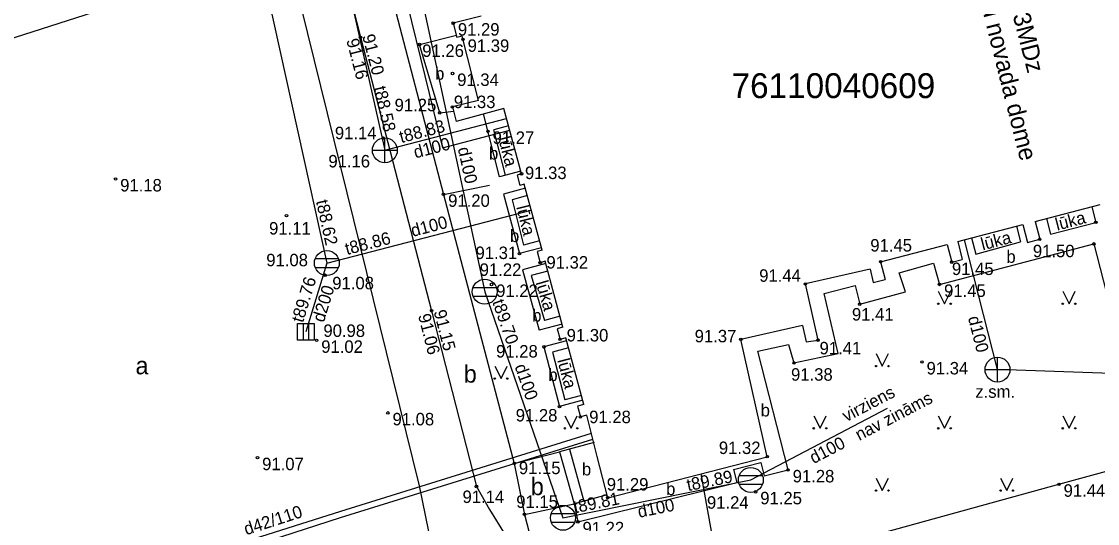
# Model space of a CAD drawing. Extents: x 634272 to 634544, y 247463 to 247653.
# Drawn here: x 634375.43 to 634418.64, y 247553.68 to 247573.83 of the extents above; entities that cross this region are included whole.
import ezdxf

# ---------------------------------------------------------------- set-up
doc = ezdxf.new("R2010")
doc.units = 0
for name, color, linetype in [('BUVE_BDET_####_####_#', 7, 'Continuous'), ('BUVE_BDET_####_TKST_#', 7, 'Continuous'), ('BUVE_EKAS_####_####_#', 7, 'Continuous'), ('BUVE_EKAS_BIZM_TKST_#', 7, 'Continuous'), ('BUVE_EKAS_RAKS_TKST_#', 7, 'Continuous'), ('CELI_CAPM_####_####_#', 7, 'Continuous'), ('CELI_CMAL_####_####_#', 7, 'Continuous'), ('CELI_CSEG_####_TKST_#', 7, 'Continuous'), ('ELEK_VADP_ZSPR_####_#', 7, 'Continuous'), ('LKAN_ELEM_####_####_#', 7, 'Continuous'), ('LKAN_ELEM_PAST_TKST_#', 7, 'Continuous'), ('LKAN_VADP_PAST_####_#', 7, 'Continuous'), ('LKAN_VADP_PAST_TKST_#', 7, 'Continuous'), ('RELJ_AATZ_####_TKST_#', 7, 'Continuous'), ('RELJ_ELEM_####_####_#', 7, 'Continuous'), ('ROBZ_KADS_####_TKST_#', 7, 'Continuous'), ('SILT_VADP_UDEN_####_#', 7, 'Continuous'), ('SILT_VADP_UDEN_TKST_#', 7, 'Continuous'), ('SKAN_ELEM_####_####_#', 7, 'Continuous'), ('SKAN_ELEM_PAST_TKST_#', 7, 'Continuous'), ('SKAN_VADP_PAST_####_#', 7, 'Continuous'), ('SKAN_VADP_PAST_TKST_#', 7, 'Continuous'), ('TERT_ELEM_####_####_#', 7, 'Continuous'), ('UDTK_VADP_NEDR_####_#', 7, 'Continuous'), ('UDTK_VADP_UDEN_####_#', 7, 'Continuous')]:
    doc.layers.add(name, color=color, linetype=linetype)

msp = doc.modelspace()

# ---------------------------------------------------------------- linework, layer by layer
at = {"layer": 'BUVE_BDET_####_####_#'}
for p, q in [((634394.989, 247569.64), (634394.404, 247569.482)), ((634394.865, 247567.656), (634394.404, 247569.482)), ((634395.48, 247567.827), (634394.623, 247567.595)), ((634395.665, 247567.141), (634394.783, 247566.902)), ((634395.746, 247566.844), (634395.133, 247566.678)), ((634418.412, 247566.397), (634418.576, 247565.768)), ((634415.389, 247565.61), (634415.553, 247564.98)), ((634416.592, 247565.923), (634416.756, 247565.292)), ((634396.312, 247564.751), (634395.427, 247564.512)), ((634396.236, 247565.032), (634395.59, 247564.857)), ((634413.588, 247565.141), (634413.758, 247564.489)), ((634396.485, 247564.111), (634395.553, 247563.859)), ((634396.566, 247563.811), (634395.902, 247563.631)), ((634397.141, 247561.686), (634396.223, 247561.438)), ((634397.056, 247561.999), (634396.43, 247561.83)), ((634397.322, 247561.016), (634396.412, 247560.77)), ((634397.398, 247560.737), (634396.749, 247560.561)), ((634397.916, 247558.82), (634397.253, 247558.641)), ((634397.969, 247558.625), (634397.035, 247558.372)), ((634398.427, 247556.933), (634397.042, 247556.558)), ((634397.432, 247556.663), (634398.017, 247554.574)), ((634404.03, 247555.842), (634405.124, 247556.123)), ((634405.124, 247556.123), (634405.26, 247555.594)), ((634404.03, 247555.842), (634404.163, 247555.323)), ((634398.948, 247554.826), (634397.627, 247554.469)), ((634397.627, 247554.469), (634397.775, 247553.745))]:
    msp.add_line(p, q, dxfattribs=at)
for points in [[(634392.223, 247570.162), (634391.414, 247572.908), (634392.893, 247573.281)], [(634392.223, 247570.162), (634392.776, 247570.234)], [(634394.623, 247567.595), (634393.985, 247570.121)], [(634394.783, 247566.902), (634395.427, 247564.512)], [(634395.133, 247566.678), (634395.59, 247564.857)], [(634416.756, 247565.292), (634418.576, 247565.768)], [(634406.216, 247555.83), (634405.003, 247560.603), (634406.24, 247560.87), (634406.454, 247560.126), (634408.225, 247560.507), (634407.669, 247562.916), (634408.905, 247563.238), (634409.092, 247562.484), (634410.939, 247562.975), (634410.684, 247563.745), (634412.053, 247564.132), (634412.297, 247563.275), (634418.496, 247564.903), (634419.89, 247559.492), (634422.401, 247560.131), (634422.592, 247559.464)], [(634413.758, 247564.489), (634415.553, 247564.98)], [(634395.553, 247563.859), (634396.223, 247561.438)], [(634395.902, 247563.631), (634396.43, 247561.83)], [(634396.412, 247560.77), (634397.035, 247558.372)], [(634396.749, 247560.561), (634397.253, 247558.641)], [(634397.042, 247556.558), (634397.627, 247554.469)], [(634405.26, 247555.594), (634406.216, 247555.83)], [(634397.775, 247553.745), (634404.163, 247555.323)]]:
    msp.add_lwpolyline(points, dxfattribs=at)
at = {"layer": 'BUVE_EKAS_####_####_#'}
for p, q in [((634393.887, 247574.04), (634392.768, 247573.764)), ((634393.126, 247573.244), (634392.916, 247573.19)), ((634393.779, 247570.663), (634393.126, 247573.244)), ((634393.779, 247570.663), (634392.734, 247570.399)), ((634394.799, 247570.341), (634392.88, 247569.822)), ((634395.51, 247567.715), (634395.333, 247567.667)), ((634395.623, 247567.295), (634395.443, 247567.247)), ((634415.648, 247565.677), (634415.834, 247564.962)), ((634416.138, 247565.805), (634416.324, 247565.09)), ((634412.601, 247564.884), (634412.788, 247564.169)), ((634413.028, 247564.995), (634413.214, 247564.28)), ((634396.337, 247564.656), (634396.135, 247564.602)), ((634396.135, 247564.602), (634396.254, 247564.149)), ((634396.46, 247564.205), (634396.254, 247564.149)), ((634409.511, 247563.883), (634406.911, 247563.295)), ((634409.511, 247563.883), (634409.632, 247563.347)), ((634409.932, 247564.189), (634410.112, 247563.472)), ((634397.175, 247561.56), (634396.947, 247561.498)), ((634396.947, 247561.498), (634397.059, 247561.07)), ((634406.798, 247561.628), (634404.32, 247561.069)), ((634406.798, 247561.628), (634406.947, 247560.969)), ((634397.291, 247561.133), (634397.059, 247561.07)), ((634398.015, 247558.453), (634397.761, 247558.384)), ((634397.761, 247558.384), (634397.873, 247557.957)), ((634398.131, 247558.027), (634397.873, 247557.957))]:
    msp.add_line(p, q, dxfattribs=at)
for points in [[(634392.768, 247573.764), (634392.916, 247573.19)], [(634392.734, 247570.399), (634392.88, 247569.822)], [(634395.51, 247567.715), (634394.799, 247570.341)], [(634395.333, 247567.667), (634395.443, 247567.247)], [(634396.337, 247564.656), (634395.623, 247567.295)], [(634416.138, 247565.805), (634418.747, 247566.484)], [(634413.028, 247564.995), (634415.648, 247565.677)], [(634409.932, 247564.189), (634412.601, 247564.884)], [(634415.834, 247564.962), (634416.324, 247565.09)], [(634412.788, 247564.169), (634413.214, 247564.28)], [(634397.175, 247561.56), (634396.46, 247564.205)], [(634409.632, 247563.347), (634410.112, 247563.472)], [(634406.947, 247560.969), (634407.421, 247561.04), (634406.911, 247563.295)], [(634398.015, 247558.453), (634397.291, 247561.133)], [(634398.975, 247554.715), (634405.382, 247556.36), (634404.32, 247561.069)], [(634398.975, 247554.715), (634398.553, 247556.371), (634398.131, 247558.027)]]:
    msp.add_lwpolyline(points, dxfattribs=at)
at = {"layer": 'CELI_CAPM_####_####_#'}
for points in [[(634386.18, 247584.245), (634386.517, 247583.098), (634389.042, 247573.196), (634391.897, 247562.219), (634393.7, 247555.164), (634394.221, 247554.237), (634394.857, 247553.225), (634395.836, 247552.623), (634399.496, 247551.073), (634400.928, 247550.806), (634417.097, 247555.253), (634426.457, 247557.809), (634427.052, 247555.379), (634437.491, 247558.047), (634462.278, 247564.311)], [(634392.378, 247566.891), (634394.229, 247567.264)]]:
    msp.add_lwpolyline(points, dxfattribs=at)
at = {"layer": 'CELI_CMAL_####_####_#'}
for points in [[(634397.071, 247591.031), (634391.102, 247589.18), (634389.241, 247588.463), (634387.877, 247587.668), (634387.466, 247585.812), (634389.236, 247579.186), (634390.091, 247575.648), (634392.378, 247566.891), (634395.219, 247556.093), (634395.631, 247554.043), (634396.02, 247552.545)], [(634395.219, 247556.093), (634397.042, 247556.558)], [(634395.631, 247554.043), (634397.627, 247554.469)]]:
    msp.add_lwpolyline(points, dxfattribs=at)
at = {"layer": 'ELEK_VADP_ZSPR_####_#'}
msp.add_lwpolyline([(634391.846, 247587.255), (634391.785, 247587.453), (634390.617, 247588.23), (634384.398, 247586.285), (634384.012, 247585.121), (634391.398, 247555.188), (634394.49, 247540.075)], dxfattribs=at)
at = {"layer": 'LKAN_ELEM_####_####_#'}
for p, q in [((634387.223, 247564.31), (634388.159, 247564.31)), ((634387.223, 247563.96), (634388.159, 247563.96)), ((634393.566, 247563.156), (634394.502, 247563.156)), ((634393.566, 247562.806), (634394.502, 247562.806)), ((634386.736, 247561.707), (634386.736, 247561.032)), ((634386.961, 247561.707), (634386.961, 247561.032)), ((634404.252, 247555.603), (634405.188, 247555.603)), ((634404.252, 247555.253), (634405.188, 247555.253)), ((634396.707, 247554.082), (634397.643, 247554.082)), ((634396.707, 247553.732), (634397.643, 247553.732))]:
    msp.add_line(p, q, dxfattribs=at)
msp.add_lwpolyline([(634386.511, 247561.707), (634387.186, 247561.707), (634387.186, 247561.032), (634386.511, 247561.032)], close=True, dxfattribs=at)
for centre in [(634387.691, 247564.135), (634394.034, 247562.981), (634404.72, 247555.428), (634397.175, 247553.907)]:
    msp.add_circle(centre, 0.5, dxfattribs=at)
at = {"layer": 'LKAN_VADP_PAST_####_#'}
for p, q in [((634381.824, 247590.733), (634387.691, 247564.135)), ((634389.021, 247586.29), (634394.034, 247562.981)), ((634387.691, 247564.135), (634386.849, 247561.369)), ((634394.034, 247562.981), (634397.175, 247553.907)), ((634397.175, 247553.907), (634404.72, 247555.428))]:
    msp.add_line(p, q, dxfattribs=at)
for points in [[(634387.691, 247564.135), (634395.903, 247566.26)], [(634404.72, 247555.428), (634410.216, 247558.304)]]:
    msp.add_lwpolyline(points, dxfattribs=at)
at = {"layer": 'RELJ_ELEM_####_####_#'}
for centre in [(634392.768, 247573.764), (634389.042, 247573.196), (634391.414, 247572.908), (634393.16, 247573.111), (634392.741, 247571.742), (634392.734, 247570.399), (634392.223, 247570.162), (634394.163, 247569.417), (634389.965, 247569.144), (634395.51, 247567.715), (634379.205, 247567.507), (634392.378, 247566.891), (634386.071, 247566.034), (634418.576, 247565.768), (634416.324, 247565.09), (634418.496, 247564.903), (634395.427, 247564.512), (634396.261, 247564.151), (634409.932, 247564.189), (634412.788, 247564.169), (634387.626, 247563.645), (634394.307, 247563.272), (634406.911, 247563.295), (634412.297, 247563.275), (634391.897, 247562.219), (634409.092, 247562.484), (634387.28, 247561.03), (634397.059, 247561.07), (634404.32, 247561.069), (634407.421, 247561.04), (634396.412, 247560.77), (634406.454, 247560.126), (634411.593, 247560.163), (634397.035, 247558.372), (634390.144, 247558.119), (634397.873, 247557.957), (634384.907, 247556.32), (634395.219, 247556.093), (634405.382, 247556.36), (634406.216, 247555.83), (634393.7, 247555.164), (634417.097, 247555.253), (634404.914, 247554.949), (634398.975, 247554.715), (634395.631, 247554.043), (634397.775, 247553.745)]:
    msp.add_circle(centre, 0.05, dxfattribs=at)
at = {"layer": 'SILT_VADP_UDEN_####_#'}
msp.add_line((634402.715, 247555.675), (634405.012, 247543.016), dxfattribs=at)
for points in [[(634375.66, 247548.71), (634375.865, 247548.771), (634375.478, 247550.132), (634388.249, 247554.171), (634398.315, 247557.303)], [(634376.217, 247548.559), (634376.441, 247548.623), (634376.038, 247549.97), (634388.236, 247553.927), (634398.375, 247557.07)]]:
    msp.add_lwpolyline(points, dxfattribs=at)
at = {"layer": 'SKAN_ELEM_####_####_#'}
for p, q in [((634390.021, 247568.162), (634390.021, 247569.162)), ((634389.521, 247568.662), (634390.521, 247568.662)), ((634414.627, 247559.359), (634414.627, 247560.359)), ((634414.127, 247559.859), (634415.127, 247559.859))]:
    msp.add_line(p, q, dxfattribs=at)
for centre in [(634390.021, 247568.662), (634414.627, 247559.859)]:
    msp.add_circle(centre, 0.5, dxfattribs=at)
at = {"layer": 'SKAN_VADP_PAST_####_#'}
for p, q in [((634386.413, 247584.687), (634390.021, 247568.662)), ((634390.021, 247568.662), (634394.908, 247569.941))]:
    msp.add_line(p, q, dxfattribs=at)
msp.add_lwpolyline([(634435.579, 247559.128), (634414.627, 247559.859), (634413.306, 247565.067)], dxfattribs=at)
at = {"layer": 'TERT_ELEM_####_####_#'}
for p, q in [((634412.25, 247563), (634412.5, 247562.5)), ((634412.5, 247562.5), (634412.75, 247563)), ((634417.25, 247563), (634417.5, 247562.5)), ((634417.5, 247562.5), (634417.75, 247563)), ((634409.75, 247560.5), (634410, 247560)), ((634410, 247560), (634410.25, 247560.5)), ((634394.437, 247559.997), (634394.687, 247559.497)), ((634394.687, 247559.497), (634394.937, 247559.997)), ((634397.25, 247558), (634397.5, 247557.5)), ((634397.5, 247557.5), (634397.75, 247558)), ((634407.25, 247558), (634407.5, 247557.5)), ((634407.5, 247557.5), (634407.75, 247558)), ((634412.25, 247558), (634412.5, 247557.5)), ((634412.5, 247557.5), (634412.75, 247558)), ((634417.25, 247558), (634417.5, 247557.5)), ((634417.5, 247557.5), (634417.75, 247558)), ((634409.75, 247555.5), (634410, 247555)), ((634410, 247555), (634410.25, 247555.5)), ((634414.75, 247555.5), (634415, 247555)), ((634415, 247555), (634415.25, 247555.5))]:
    msp.add_line(p, q, dxfattribs=at)
for centre, radius in [((634412.25, 247562.5), 0.028), ((634412.75, 247562.5), 0.0263), ((634417.25, 247562.5), 0.028), ((634417.75, 247562.5), 0.0263), ((634409.75, 247560), 0.028), ((634410.25, 247560), 0.0263), ((634394.437, 247559.496), 0.028), ((634394.937, 247559.496), 0.0263), ((634397.25, 247557.5), 0.028), ((634397.75, 247557.5), 0.0263), ((634407.25, 247557.5), 0.028), ((634407.75, 247557.5), 0.0263), ((634412.25, 247557.5), 0.028), ((634412.75, 247557.5), 0.0263), ((634417.25, 247557.5), 0.028), ((634417.75, 247557.5), 0.0263), ((634409.75, 247555), 0.028), ((634410.25, 247555), 0.0263), ((634414.75, 247555), 0.028), ((634415.25, 247555), 0.0263)]:
    msp.add_circle(centre, radius, dxfattribs=at)
at = {"layer": 'UDTK_VADP_NEDR_####_#'}
msp.add_lwpolyline([(634381.084, 247599.023), (634386.736, 247576.903), (634349.56, 247564.99), (634353.161, 247551.069), (634367.117, 247543.476), (634370.735, 247530.054)], dxfattribs=at)
at = {"layer": 'UDTK_VADP_UDEN_####_#'}
msp.add_lwpolyline([(634384.535, 247600.557), (634392.34, 247568.756), (634395.036, 247569.467)], dxfattribs=at)

# ---------------------------------------------------------------- texts
at = {"layer": 'BUVE_BDET_####_TKST_#'}
for p in [(634392.039, 247571.492), (634394.205, 247568.288), (634395.048, 247564.976), (634414.985, 247564.141), (634395.942, 247561.783), (634396.589, 247559.397), (634405.116, 247557.977), (634397.937, 247555.609), (634401.317, 247554.819)]:
    msp.add_text('b', height=0.5, dxfattribs=at).set_placement(p)
for rotation, p in [(284.1694, (634394.57, 247569.155)), (284.0881, (634395.295, 247566.386)), (14.5931, (634417.023, 247565.433)), (14.5931, (634414.033, 247564.638)), (286.3396, (634396.074, 247563.351)), (284.7083, (634396.942, 247560.236))]:
    msp.add_text('lūka', height=0.5, rotation=rotation, dxfattribs=at).set_placement(p)
at = {"layer": 'BUVE_EKAS_BIZM_TKST_#'}
msp.add_text('Līvānu novada dome', height=0.7, rotation=284.1272, dxfattribs=at).set_placement((634413.417, 247576.666))
at = {"layer": 'BUVE_EKAS_RAKS_TKST_#'}
msp.add_text('3MDz', height=0.7, rotation=284.4886, dxfattribs=at).set_placement((634415.234, 247574.079))
at = {"layer": 'CELI_CSEG_####_TKST_#'}
for s, p in [('a', (634380.007, 247559.669)), ('b', (634393.192, 247559.334)), ('b', (634395.885, 247554.816))]:
    msp.add_text(s, height=0.7, dxfattribs=at).set_placement(p)
at = {"layer": 'LKAN_ELEM_PAST_TKST_#'}
for s, p in [(' 91.08', (634385.074, 247564.005)), (' 91.22', (634393.645, 247563.62)), (' 90.98', (634387.368, 247561.169)), (' 91.24', (634402.773, 247554.274))]:
    msp.add_text(s, height=0.5, dxfattribs=at).set_placement(p)
at = {"layer": 'LKAN_VADP_PAST_TKST_#'}
for s, rotation, p in [('d100', 282.1376, (634392.949, 247568.738)), ('t88.62', 282.4391, (634387.252, 247566.618)), ('d100', 14.5093, (634391.14, 247565.183)), ('t88.86', 14.5093, (634388.496, 247564.452)), ('t89.76', 73.0692, (634386.733, 247561.713)), ('d200', 73.0692, (634387.57, 247561.725)), ('t89.70', 289.0935, (634394.329, 247562.578)), ('d100', 289.0935, (634395.229, 247559.987)), ('virziens', 27.6286, (634408.555, 247557.742)), ('nav zināms', 27.6286, (634409.076, 247556.99)), ('d100', 27.6286, (634407.244, 247556.061)), ('t89.89', 11.3975, (634402.2, 247554.975)), ('t89.81', 11.3975, (634397.654, 247554.089)), ('d100', 11.3975, (634400.23, 247553.907))]:
    msp.add_text(s, height=0.5, rotation=rotation, dxfattribs=at).set_placement(p)
at = {"layer": 'RELJ_AATZ_####_TKST_#'}
for s, p in [(' 91.29', (634392.768, 247573.264)), (' 91.39', (634393.16, 247572.611)), (' 91.26', (634391.338, 247572.408)), (' 91.34', (634392.741, 247571.242)), (' 91.33', (634392.605, 247570.354)), (' 91.25', (634390.228, 247570.227)), (' 91.14', (634387.829, 247569.106)), (' 91.27', (634394.163, 247568.917)), (' 91.33', (634395.463, 247567.505)), (' 91.18', (634379.205, 247567.007)), (' 91.20', (634392.378, 247566.391)), (' 91.11', (634385.187, 247565.279)), (' 91.31', (634393.477, 247564.295)), (' 91.45', (634409.334, 247564.595)), (' 91.50', (634415.863, 247564.368)), (' 91.32', (634396.326, 247563.912)), (' 91.44', (634404.871, 247563.382)), (' 91.45', (634412.613, 247563.653)), (' 91.08', (634387.725, 247563.079)), (' 91.22', (634394.307, 247562.772)), (' 91.45', (634412.297, 247562.775)), (' 91.41', (634408.596, 247561.826)), (' 91.30', (634397.138, 247560.987)), (' 91.37', (634402.28, 247560.952)), (' 91.02', (634387.28, 247560.53)), (' 91.28', (634394.304, 247560.342)), (' 91.41', (634407.296, 247560.469)), (' 91.34', (634411.593, 247559.663)), (' 91.38', (634406.15, 247559.412)), (' 91.28', (634395.093, 247557.775)), (' 91.08', (634390.144, 247557.619)), (' 91.28', (634398.043, 247557.708)), (' 91.32', (634403.251, 247556.468)), (' 91.07', (634384.907, 247555.82)), (' 91.15', (634395.219, 247555.661)), (' 91.28', (634406.216, 247555.33)), (' 91.29', (634398.748, 247555.004)), (' 91.44', (634417.097, 247554.753)), (' 91.14', (634392.955, 247554.502)), (' 91.15', (634395.114, 247554.306)), (' 91.25', (634404.914, 247554.449)), (' 91.22', (634397.775, 247553.245))]:
    msp.add_text(s, height=0.5, dxfattribs=at).set_placement(p)
for s, rotation, p in [(' 91.16', 284.579, (634388.423, 247573.258)), (' 91.20', 284.579, (634389.061, 247573.431)), (' 91.15', 284.3359, (634391.933, 247562.37)), (' 91.06', 284.3359, (634391.306, 247562.214))]:
    msp.add_text(s, height=0.5, rotation=rotation, dxfattribs=at).set_placement(p)
at = {"layer": 'ROBZ_KADS_####_TKST_#'}
msp.add_text('76110040609', height=1, dxfattribs=at).set_placement((634403.947, 247570.754))
at = {"layer": 'SILT_VADP_UDEN_TKST_#'}
msp.add_text('d42/110', height=0.5, rotation=17.9729, dxfattribs=at).set_placement((634384.455, 247553.204))
at = {"layer": 'SKAN_ELEM_PAST_TKST_#'}
for s, p in [(' 91.16', (634387.569, 247567.972)), ('z.sm.', (634413.736, 247558.724))]:
    msp.add_text(s, height=0.5, dxfattribs=at).set_placement(p)
at = {"layer": 'SKAN_VADP_PAST_TKST_#'}
for s, rotation, p in [('t88.58', 282.6885, (634389.577, 247571.175)), ('t88.83', 14.662, (634390.677, 247568.945)), ('d100', 14.662, (634391.251, 247568.33)), ('d100', 284.2354, (634413.439, 247561.943))]:
    msp.add_text(s, height=0.5, rotation=rotation, dxfattribs=at).set_placement(p)

doc.saveas('drawing.dxf')
